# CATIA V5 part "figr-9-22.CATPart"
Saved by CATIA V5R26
Part number: Part3
Bounding box of the stored display mesh (mm): x -112 to 0, y -101.683 to 103.294, z -80.304 to 44.415
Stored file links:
  D:\_Deepak\CATIA\CATIA V5-6R2016_Deepak\Resources\Part files\Partfiles\c09_catia_v5_6r2016_prt\figr-9-22.CATPart
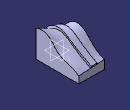
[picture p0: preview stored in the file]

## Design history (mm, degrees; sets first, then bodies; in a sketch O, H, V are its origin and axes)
Set1
  Plane1: type Offset, RefPlane yz-plane, Offset -112
  Plane2: type Offset, RefPlane yz-plane, Offset -63
  Plane3: type Normal, Curve Sketch4, RefPoint vertex of Sketch4
Body1 (main body)
  Sketch1 on yz-plane, origin (0, 0, 0), H (0, 1, 0), V (0, 0, 1)
    spline S1 through (-92.6897, 40.1119) (-30, 30) (10, -10) (60, -30) (97.3103, -50.3041)
    line L1 (97.3103, -50.3041) -> (97.3103, -80.3041)
    line L2 (97.3103, -80.3041) -> (-92.6897, -80.3041)
    line L3 (-92.6897, -80.3041) -> (-92.6897, 40.1119)
    point P3 (-92.6897, 40.1119)
    point P4 (97.3103, -50.3041)
    point P5 (-92.6897, 40.1119)
    point P6 (97.3103, -50.3041)
    vertical: L1 V, L3 V
    horizontal: L2 H
    coincidence: P5 P3, P6 P4
  Sketch2 on Plane1, origin (-112, 0, 0), H (0, 1, 0), V (0, 0, 1)
    spline S1 through (-90, -30) (-70, 10) (-20, 40) (40, 0) (100, -40)
    line L1 (100, -40) -> (100, -80)
    line L2 (100, -80) -> (-90, -80)
    line L3 (-90, -80) -> (-90, -30)
    point P3 (-90, -30)
    point P4 (100, -40)
    point P5 (40, 0)
    point P6 (-90, -30)
    point P7 (100, -40)
    coincidence: P5 H, P6 P3, P7 P4
    vertical: L1 V, L3 V
    horizontal: L2 H
  Loft1: Sections (Sketch1; Sketch2)
  Sketch3 on Plane3, origin (0, -40.1726, -44.9298), H (1, 0, 0), V (0, -0.7455, 0.6665)
    point P1 (-63, 68.4187)
    line L1 (-63, 68.4187) -> (-75.2117, 62.4925)
    line L2 (-75.2117, 62.4925) -> (-79.6266, 71.5898)
    line L3 (-79.6266, 71.5898) -> (-57.1205, 82.5119)
    line L4 (-57.1205, 82.5119) -> (-52.7056, 73.4145)
    point P5 (-52.7056, 73.4145)
    line L5 (-52.7056, 73.4145) -> (-63, 68.4187)
    reference projected point E1 (-63, 68.4187) from vertex of Sketch4
    perpendicularity: L2 L1
    parallelism: L3 L1, L4 L2, L5 L1
    coincidence: P5 L1, P1 E1
  Sketch4 on Plane2, origin (-63, 0, 0), H (0, 1, 0), V (0, 0, 1)
    intersected curve E1 from face of Loft1
  Rib1: profile Sketch3, centre curve Sketch4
